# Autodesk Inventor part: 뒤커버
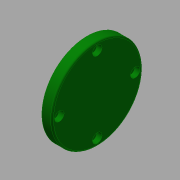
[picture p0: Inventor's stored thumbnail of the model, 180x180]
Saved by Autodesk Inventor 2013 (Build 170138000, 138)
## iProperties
Created: 2015-09
Part Number: 뒤커버
Material: 알루미늄 6061
Document SubType Name: Modeling
Designer: mduedu
Density: 2.71 g/cm^3
Mass: 54.0417 g
Surface Area: 84.9688 cm^2
Volume: 19.9416 cm^3
Author: mduedu
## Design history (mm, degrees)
sketch "스케치1"
  geometry: L1 (-15.5, 47)-(-15.5, 78); L2 (-15.5, 78)-(-22.5, 78); L3 (-22.5, 78)-(-22.5, 67); L4 (-25.5, 67)-(-25.5, 47); L5 (-79.5, 39.5)-(-79.5, 54.5) reference; L6 (48.5, 54.5)-(48.5, 39.5) reference; L7 (-79.5, 47)-(48.5, 47); L8 (-22.5, 67)-(-25.5, 67); L9 (-25.5, 47)-(-15.5, 47); 1 further point
  constraints: 14 end point, 4 midpoint, 3 parallel, 1 collinear, 1 point on line, 1 vertical
  dimensions: "d6" = 62 diameter of L2 L7; "d7" = 7 distance of L1.end L2.end; "d8" = 40 diameter of L3.end L7; "d32" = 10 distance between parallel lines of L1 L4
revolve "회전1" sketch "스케치1" stored, may be unused: angle "d4" = 90 deg
sketch "스케치4"
  geometry: C1 r 31 at (0, 0) reference; 2 further points
  constraints: 1 coincident
hole "구멍3" sketch "스케치4" at (0, 0) diameter "d33" = 33; stored, may be unused: countersink angle "d37" = 90 deg, drill point angle "d39" = 0 deg; dims "d34" = 6, "d35" = 4, "d36" = 2, "d38" = 5
fillet "모깎기4" dims "d40" = 1
chamfer "모따기2" distance "d41" = 1; stored, may be unused: second distance "d42" = 2, angle "d43" = 45 deg
sketch "스케치6" dims "d56" = 52
  geometry: C1 r 31 at (0, 0) reference; 5 further points
  constraints: 2 vertical alignment, 1 coincident, 7 other
  dimensions: "d59" = 360 deg dimension on C1.centre point (0, 26) (derived)
hole "구멍4" sketch "스케치6" at (0, 26), (-26, 0), (0, -26), (26, 0) diameter "d49" = 3.4; stored, may be unused: countersink angle "d53" = 90 deg, drill point angle "d55" = 0 deg; dims "d50" = 6, "d51" = 6.5, "d52" = 3.4, "d54" = 8
node "솔리드1"
node "참조1"
node "참조2"
